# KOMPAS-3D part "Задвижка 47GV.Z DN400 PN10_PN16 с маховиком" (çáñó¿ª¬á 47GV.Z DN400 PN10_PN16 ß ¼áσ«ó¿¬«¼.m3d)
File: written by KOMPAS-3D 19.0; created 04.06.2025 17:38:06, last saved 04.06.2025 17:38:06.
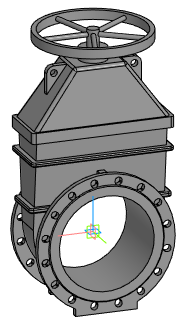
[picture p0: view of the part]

Document properties: Автор: Евгений; Полное имя файла: E:\Dendor Работа Сачек\3D для проекитирвщиков\2.1 Тип 47GV, 47GV.Z Задвижка клиновая фланцевая с обрезиненным клином\stp_Тип 47GV.Z. Задвижка DN40-DN350 с маховиком\Задвижка 47GV.Z DN400 PN10_PN16 с маховиком.m3d

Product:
- Part/product: Задвижка 47GV.Z DN400 PN10_PN16 с маховиком

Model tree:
1. Операция без истории:1  (labels: Задвижка 47GV.Z DN400 PN10_PN16 с маховиком)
